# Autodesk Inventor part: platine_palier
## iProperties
Shininess: 64.0
Length Units: 11269
Angle Units: 11279
Time Units: 11290
Mass Units: 11283
Length Display Precision: 3
Angle Display Precision: 2
Compacted: True
Part Number: platine_palier
Document SubType Name: Modeling
Created: 2004-05
Material: Par défaut
Designer: David
Density: 0.0
Volumn: 0.0
Area: 0.0
PropertySet Name: Model Information
Control State: 0
Master: False
Checked Out: False
Author: David
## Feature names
1. Extrusion1
2. Congé1 [Fillet]
3. Perçage1 [Hole]
4. Perçage2 [Hole]
